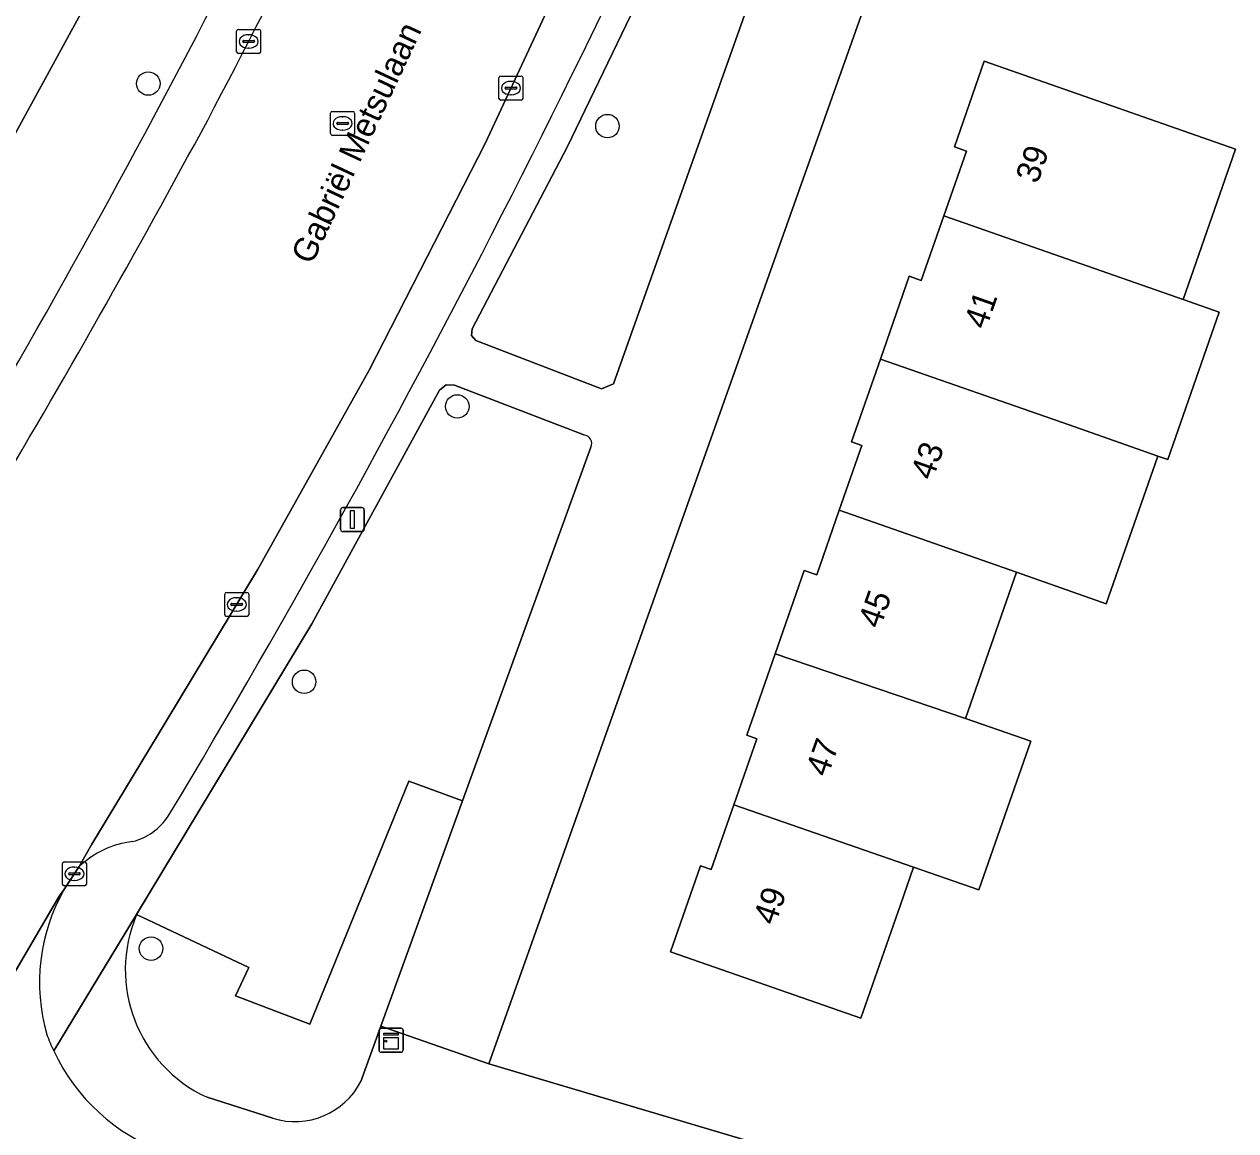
# Model space of a CAD drawing. Extents: x 161771 to 163125, y 382475 to 383179.
# Drawn here: x 162448.9 to 162499.4, y 382631.8 to 382677.9 of the extents above; entities that cross this region are included whole.
import ezdxf

# ---------------------------------------------------------------- set-up
doc = ezdxf.new("R2010")
doc.units = 0
for name, color, linetype in [('IMGEO_Boom', 7, 'Continuous'), ('IMGEO_Erf', 7, 'Continuous'), ('IMGEO_Groenvoorziening', 7, 'Continuous'), ('IMGEO_Kast', 7, 'Continuous'), ('IMGEO_Kolk', 7, 'Continuous'), ('IMGEO_Lichtmast', 7, 'Continuous'), ('IMGEO_Openbare_ruimte_label', 7, 'Continuous'), ('IMGEO_Pand', 7, 'Continuous'), ('IMGEO_Pand_nummerreeks', 7, 'Continuous'), ('IMGEO_Parkeervlak_open', 7, 'Continuous'), ('IMGEO_Rijbaan_lokaal_open', 7, 'Continuous'), ('IMGEO_Rioolput', 7, 'Continuous'), ('IMGEO_Voetpad_open', 7, 'Continuous')]:
    doc.layers.add(name, color=color, linetype=linetype)

msp = doc.modelspace()

# ---------------------------------------------------------------- linework, layer by layer
at = {"layer": 'IMGEO_Boom'}
for centre in [(162454.115, 382675.433), (162473.254, 382673.659), (162466.995, 382661.976), (162460.61, 382650.498), (162454.23, 382639.375)]:
    msp.add_circle(centre, 0.489, dxfattribs=at)
at = {"layer": 'IMGEO_Erf'}
for points in [[(162489.16, 382693.298), (162468.305, 382634.573), (162500, 382625.154)], [(162443.703, 382664.454), (162451.64, 382678.977)]]:
    msp.add_lwpolyline(points, dxfattribs=at)
msp.add_lwpolyline([(162494.048, 382653.752), (162490.306, 382655.062), (162488.177, 382648.965), (162490.896, 382648.016), (162488.733, 382641.823), (162486.015, 382642.772), (162485.465, 382641.197), (162483.816, 382636.476), (162475.887, 382639.245), (162477.138, 382642.829), (162477.58, 382642.675), (162478.521, 382645.37), (162479.482, 382648.12), (162479.059, 382648.267), (162480.242, 382651.656), (162481.457, 382655.134), (162481.976, 382654.953), (162482.917, 382657.648), (162483.858, 382660.342), (162483.424, 382660.494), (162484.63, 382663.948), (162485.835, 382667.4), (162486.331, 382667.227), (162487.272, 382669.922), (162488.215, 382672.622), (162487.714, 382672.797), (162488.958, 382676.36), (162493.679, 382674.711), (162499.437, 382672.7), (162497.246, 382666.428), (162498.756, 382665.899), (162496.613, 382659.765), (162496.202, 382659.908)], close=True, dxfattribs=at)
at = {"layer": 'IMGEO_Groenvoorziening'}
for points in [[(162475.724, 382681.413), (162471.572, 382672.776), (162467.61, 382665.208), (162467.59, 382664.935), (162467.772, 382664.73), (162473.013, 382662.713), (162473.51, 382662.915), (162479.491, 382679.788)], [(162472.269, 382660.785), (162466.878, 382662.857), (162466.525, 382662.875), (162466.257, 382662.65), (162460.926, 382652.91), (162453.63, 382640.792), (162458.301, 382638.592), (162457.753, 382637.405), (162460.849, 382636.226), (162464.97, 382646.359), (162467.218, 382645.531), (162472.565, 382660.277)], [(162467.218, 382645.531), (162464.97, 382646.359), (162460.849, 382636.226), (162457.753, 382637.405), (162458.301, 382638.592), (162453.63, 382640.792)], [(162462.978, 382633.835), (162463.814, 382636.141), (162467.218, 382645.531)], [(162456.563, 382633.183), (162459.305, 382632.306)]]:
    msp.add_lwpolyline(points, dxfattribs=at)
for centre, radius, start, end in [((162472.243, 382660.43), 0.356, 334.6119, 85.8449), ((162459, 382638.492), 5.842, 156.8173, 245.3425), ((162460.224, 382635.276), 3.109, 252.8138, 332.3883)]:
    msp.add_arc(centre, radius, start, end, dxfattribs=at)
at = {"layer": 'IMGEO_Kast'}
for p, q in [((162463.736, 382635.131), (162463.736, 382635.972)), ((162463.736, 382635.972), (162463.736, 382635.131)), ((162463.811, 382636.056), (162464.652, 382636.056)), ((162464.652, 382636.056), (162463.811, 382636.056)), ((162464.736, 382635.981), (162464.736, 382635.14)), ((162464.736, 382635.14), (162464.736, 382635.981)), ((162464.661, 382635.056), (162463.82, 382635.056)), ((162463.82, 382635.056), (162464.661, 382635.056))]:
    msp.add_line(p, q, dxfattribs=at)
for points in [[(162463.931, 382635.846), (162464.531, 382635.846), (162464.531, 382635.761), (162463.931, 382635.761), (162463.931, 382635.846)], [(162463.931, 382635.671), (162464.531, 382635.671), (162464.531, 382635.182), (162463.931, 382635.182), (162463.931, 382635.671)]]:
    msp.add_lwpolyline(points, dxfattribs=at)
msp.add_circle((162464.015, 382635.52), 0.0377, dxfattribs=at)
for centre, start, end in [((162463.814, 382635.978), 92.4484, 184.2845), ((162463.814, 382635.978), 92.4484, 184.2845), ((162464.658, 382635.978), 2.4484, 94.2845), ((162464.658, 382635.978), 2.4484, 94.2845), ((162463.814, 382635.134), 182.4484, 274.2845), ((162463.814, 382635.134), 182.4484, 274.2845), ((162464.658, 382635.134), 272.4484, 4.2845), ((162464.658, 382635.134), 272.4484, 4.2845)]:
    msp.add_arc(centre, 0.0779, start, end, dxfattribs=at)
at = {"layer": 'IMGEO_Kolk'}
for p, q in [((162457.873, 382677.688), (162458.725, 382677.688)), ((162457.798, 382676.762), (162457.798, 382677.614)), ((162458.057, 382677.182), (162458.057, 382677.194)), ((162458.495, 382677.145), (162458.097, 382677.145)), ((162458.1, 382677.231), (162458.498, 382677.231)), ((162458.286, 382677.468), (162458.311, 382677.468)), ((162458.541, 382677.194), (162458.541, 382677.182)), ((162458.799, 382677.614), (162458.799, 382676.762)), ((162458.725, 382676.688), (162457.873, 382676.688)), ((162458.309, 382676.908), (162458.284, 382676.908)), ((162468.733, 382674.817), (162468.733, 382675.669)), ((162468.808, 382675.743), (162469.66, 382675.743)), ((162469.734, 382675.669), (162469.734, 382674.817)), ((162468.992, 382675.237), (162468.992, 382675.249)), ((162469.43, 382675.2), (162469.032, 382675.2)), ((162469.035, 382675.286), (162469.433, 382675.286)), ((162469.221, 382675.523), (162469.246, 382675.523)), ((162469.476, 382675.249), (162469.476, 382675.237)), ((162469.66, 382674.743), (162468.808, 382674.743)), ((162469.244, 382674.963), (162469.219, 382674.963)), ((162457.3, 382653.295), (162457.3, 382654.147)), ((162457.375, 382654.221), (162458.227, 382654.221)), ((162457.788, 382654.001), (162457.813, 382654.001)), ((162458.301, 382654.147), (162458.301, 382653.295)), ((162457.559, 382653.715), (162457.559, 382653.727)), ((162457.997, 382653.678), (162457.599, 382653.678)), ((162457.602, 382653.764), (162458, 382653.764)), ((162457.811, 382653.441), (162457.786, 382653.441)), ((162458.043, 382653.727), (162458.043, 382653.715)), ((162458.227, 382653.221), (162457.375, 382653.221)), ((162450.534, 382642.067), (162450.534, 382642.919)), ((162450.609, 382642.993), (162451.461, 382642.993)), ((162451.022, 382642.773), (162451.047, 382642.773)), ((162451.535, 382642.919), (162451.535, 382642.067)), ((162450.793, 382642.487), (162450.793, 382642.499)), ((162451.231, 382642.45), (162450.833, 382642.45)), ((162450.836, 382642.536), (162451.234, 382642.536)), ((162451.277, 382642.499), (162451.277, 382642.487)), ((162451.461, 382641.993), (162450.609, 382641.993)), ((162451.045, 382642.213), (162451.02, 382642.213))]:
    msp.add_line(p, q, dxfattribs=at)
for points in [[(162457.873, 382677.688), (162458.725, 382677.688)], [(162457.798, 382676.762), (162457.798, 382677.614)], [(162458.799, 382677.614), (162458.799, 382676.762)], [(162458.725, 382676.688), (162457.873, 382676.688)], [(162468.733, 382674.817), (162468.733, 382675.669)], [(162468.808, 382675.743), (162469.66, 382675.743)], [(162469.734, 382675.669), (162469.734, 382674.817)], [(162469.66, 382674.743), (162468.808, 382674.743)], [(162457.3, 382653.295), (162457.3, 382654.147)], [(162457.375, 382654.221), (162458.227, 382654.221)], [(162458.301, 382654.147), (162458.301, 382653.295)], [(162458.227, 382653.221), (162457.375, 382653.221)], [(162450.534, 382642.067), (162450.534, 382642.919)], [(162450.609, 382642.993), (162451.461, 382642.993)], [(162451.535, 382642.919), (162451.535, 382642.067)], [(162451.461, 382641.993), (162450.609, 382641.993)]]:
    msp.add_lwpolyline(points, dxfattribs=at)
for centre, radius, start, end in [((162457.875, 382677.612), 0.0765, 91.552, 178.448), ((162457.875, 382677.612), 0.0765, 91.552, 178.448), ((162458.723, 382677.612), 0.0765, 1.552, 88.448), ((162458.723, 382677.612), 0.0765, 1.552, 88.448), ((162458.097, 382677.191), 0.0403, 85.8775, 175.7526), ((162458.094, 382677.181), 0.0366, 178.938, 274.7102), ((162458.498, 382677.188), 0.043, 264.8664, 352.4533), ((162458.502, 382677.193), 0.0386, 1.7309, 96.639), ((162457.875, 382676.764), 0.0765, 181.552, 268.448), ((162457.875, 382676.764), 0.0765, 181.552, 268.448), ((162458.723, 382676.764), 0.0765, 271.552, 358.448), ((162458.723, 382676.764), 0.0765, 271.552, 358.448), ((162468.81, 382675.667), 0.0765, 91.552, 178.448), ((162468.81, 382675.667), 0.0765, 91.552, 178.448), ((162469.658, 382675.667), 0.0765, 1.552, 88.448), ((162469.658, 382675.667), 0.0765, 1.552, 88.448), ((162469.032, 382675.246), 0.0403, 85.8775, 175.7526), ((162469.029, 382675.236), 0.0366, 178.938, 274.7102), ((162469.433, 382675.243), 0.043, 264.8664, 352.4533), ((162469.437, 382675.248), 0.0386, 1.7309, 96.639), ((162468.81, 382674.819), 0.0765, 181.552, 268.448), ((162468.81, 382674.819), 0.0765, 181.552, 268.448), ((162469.658, 382674.819), 0.0765, 271.552, 358.448), ((162469.658, 382674.819), 0.0765, 271.552, 358.448), ((162457.377, 382654.145), 0.0765, 91.552, 178.448), ((162457.377, 382654.145), 0.0765, 91.552, 178.448), ((162458.225, 382654.145), 0.0765, 1.552, 88.448), ((162458.225, 382654.145), 0.0765, 1.552, 88.448), ((162457.599, 382653.724), 0.0403, 85.8775, 175.7526), ((162457.596, 382653.714), 0.0366, 178.938, 274.7102), ((162458, 382653.721), 0.043, 264.8664, 352.4533), ((162458.004, 382653.726), 0.0386, 1.7309, 96.639), ((162457.377, 382653.297), 0.0765, 181.552, 268.448), ((162457.377, 382653.297), 0.0765, 181.552, 268.448), ((162458.225, 382653.297), 0.0765, 271.552, 358.448), ((162458.225, 382653.297), 0.0765, 271.552, 358.448), ((162450.611, 382642.917), 0.0765, 91.552, 178.448), ((162450.611, 382642.917), 0.0765, 91.552, 178.448), ((162451.459, 382642.917), 0.0765, 1.552, 88.448), ((162451.459, 382642.917), 0.0765, 1.552, 88.448), ((162450.833, 382642.496), 0.0403, 85.8775, 175.7526), ((162450.83, 382642.486), 0.0366, 178.938, 274.7102), ((162451.234, 382642.493), 0.043, 264.8664, 352.4533), ((162451.238, 382642.498), 0.0386, 1.7309, 96.639), ((162450.611, 382642.069), 0.0765, 181.552, 268.448), ((162450.611, 382642.069), 0.0765, 181.552, 268.448), ((162451.459, 382642.069), 0.0765, 271.552, 358.448), ((162451.459, 382642.069), 0.0765, 271.552, 358.448)]:
    msp.add_arc(centre, radius, start, end, dxfattribs=at)
for centre, major_axis, ratio, start_param, end_param in [((162458.285, 382677.188), (-0.387, 0.002), 0.722429, 4.712389, 7.853982), ((162458.31, 382677.188), (-0.39, 0.002), 0.717154, 1.570796, 4.712389), ((162469.22, 382675.243), (-0.387, 0.002), 0.722429, 4.712389, 7.853982), ((162469.245, 382675.243), (-0.39, 0.002), 0.717154, 1.570796, 4.712389), ((162457.787, 382653.721), (-0.387, 0.002), 0.722429, 4.712389, 7.853982), ((162457.812, 382653.721), (-0.39, 0.002), 0.717154, 1.570796, 4.712389), ((162451.021, 382642.493), (-0.387, 0.002), 0.722429, 4.712389, 7.853982), ((162451.046, 382642.493), (-0.39, 0.002), 0.717154, 1.570796, 4.712389)]:
    msp.add_ellipse(centre, major_axis=major_axis, ratio=ratio, start_param=start_param, end_param=end_param, dxfattribs=at)
at = {"layer": 'IMGEO_Lichtmast'}
for p, q in [((162462.129, 382656.86), (162462.129, 382657.66)), ((162462.129, 382657.66), (162462.129, 382656.86)), ((162462.229, 382657.76), (162463.019, 382657.76)), ((162463.019, 382657.76), (162462.229, 382657.76)), ((162463.119, 382657.66), (162463.119, 382656.86)), ((162463.119, 382656.86), (162463.119, 382657.66)), ((162463.019, 382656.76), (162462.229, 382656.76)), ((162462.229, 382656.76), (162463.019, 382656.76))]:
    msp.add_line(p, q, dxfattribs=at)
msp.add_lwpolyline([(162462.549, 382657.635), (162462.699, 382657.635), (162462.699, 382656.885), (162462.549, 382656.885), (162462.549, 382657.635)], dxfattribs=at)
for centre, start, end in [((162462.229, 382657.66), 90, 180), ((162462.229, 382657.66), 90, 180), ((162463.019, 382657.66), 0, 90), ((162463.019, 382657.66), 360, 90), ((162462.229, 382656.86), 180, 270), ((162462.229, 382656.86), 180, 270), ((162463.019, 382656.86), 270, 0), ((162463.019, 382656.86), 270, 0)]:
    msp.add_arc(centre, 0.1, start, end, dxfattribs=at)
at = {"layer": 'IMGEO_Pand'}
for points in [[(162497.246, 382666.428), (162499.437, 382672.7), (162493.679, 382674.711), (162488.958, 382676.36), (162487.714, 382672.797), (162488.215, 382672.622), (162487.272, 382669.922)], [(162498.756, 382665.899), (162497.246, 382666.428), (162487.272, 382669.922), (162486.331, 382667.227), (162485.835, 382667.4), (162484.63, 382663.948), (162492.456, 382661.217), (162495.103, 382660.292), (162496.202, 382659.908), (162496.613, 382659.765)], [(162496.202, 382659.908), (162495.103, 382660.292), (162492.456, 382661.217), (162484.63, 382663.948), (162483.424, 382660.494), (162483.858, 382660.342), (162482.917, 382657.648), (162490.306, 382655.062), (162494.048, 382653.752)], [(162488.177, 382648.965), (162490.306, 382655.062), (162482.917, 382657.648), (162481.976, 382654.953), (162481.457, 382655.134), (162480.242, 382651.656)], [(162488.177, 382648.965), (162480.242, 382651.656), (162479.059, 382648.267), (162479.482, 382648.12), (162478.521, 382645.37), (162486.015, 382642.772), (162488.733, 382641.823), (162490.896, 382648.016)], [(162478.521, 382645.37), (162477.58, 382642.675), (162477.138, 382642.829), (162475.887, 382639.245), (162483.816, 382636.476), (162485.465, 382641.197), (162486.015, 382642.772)]]:
    msp.add_lwpolyline(points, close=True, dxfattribs=at)
at = {"layer": 'IMGEO_Parkeervlak_open'}
msp.add_lwpolyline([(162512.632, 382808.546), (162511.28, 382810.646), (162509.154, 382801.926), (162505.086, 382785.036), (162500.442, 382764.689), (162500, 382762.664), (162498.277, 382754.772), (162497.178, 382750), (162496.887, 382748.736), (162496.008, 382745.127), (162493.813, 382737.211), (162492.079, 382731.423), (162488.748, 382721.634), (162487.266, 382717.521), (162483.52, 382707.553), (162479.897, 382698.492), (162476.717, 382691.181), (162472.466, 382682.195), (162468.158, 382672.932), (162463.316, 382663.492), (162458.673, 382655.168), (162454.89, 382648.901), (162451.763, 382643.729), (162451.23, 382642.792)], dxfattribs=at)
for centre, radius, start, end in [((162182.598, 382819.036), 310.052, 332.0916, 339.45199), ((162091.344, 382862.892), 423.95, 329.05493, 337.05894), ((162116.582, 382854.367), 382.886, 329.58715, 333.2852), ((162074.96, 382879.557), 433.51, 326.74218, 331.68168), ((162452.816, 382646.334), 2.575, 284.5682, 325.9064), ((162453.965, 382639.871), 4.001, 97.1898, 133.1161)]:
    msp.add_arc(centre, radius, start, end, dxfattribs=at)
at = {"layer": 'IMGEO_Rijbaan_lokaal_open'}
for points in [[(162404.135, 382574.905), (162406.193, 382577.683), (162407.992, 382580.104), (162411.216, 382584.51), (162411.282, 382584.599), (162428.004, 382607.232), (162439.892, 382623.551), (162440.057, 382623.883), (162450.381, 382641.534), (162450.597, 382641.828), (162451.23, 382642.792), (162451.763, 382643.729), (162454.89, 382648.901), (162458.673, 382655.168), (162463.316, 382663.492), (162468.158, 382672.932), (162472.466, 382682.195)], [(162450.597, 382641.828), (162450.381, 382641.534), (162440.057, 382623.883), (162439.892, 382623.551)]]:
    msp.add_lwpolyline(points, dxfattribs=at)
for centre, radius, start, end in [((162182.598, 382819.036), 310.052, 332.0916, 339.45199), ((162074.96, 382879.557), 433.51, 326.74218, 331.68168), ((162457.39, 382637.972), 7.811, 150.4156, 196.179), ((162457.259, 382638.46), 7.838, 199.8736, 205.2827), ((162457.608, 382638.596), 8.212, 205.1066, 249.9523)]:
    msp.add_arc(centre, radius, start, end, dxfattribs=at)
at = {"layer": 'IMGEO_Rioolput'}
for p, q in [((162461.715, 382673.346), (162461.715, 382674.198)), ((162461.79, 382674.272), (162462.642, 382674.272)), ((162462.716, 382674.198), (162462.716, 382673.346)), ((162461.974, 382673.766), (162461.974, 382673.778)), ((162462.412, 382673.729), (162462.014, 382673.729)), ((162462.017, 382673.815), (162462.415, 382673.815)), ((162462.203, 382674.052), (162462.228, 382674.052)), ((162462.458, 382673.778), (162462.458, 382673.766)), ((162462.642, 382673.272), (162461.79, 382673.272)), ((162462.226, 382673.492), (162462.201, 382673.492))]:
    msp.add_line(p, q, dxfattribs=at)
for points in [[(162461.715, 382673.346), (162461.715, 382674.198)], [(162461.79, 382674.272), (162462.642, 382674.272)], [(162462.716, 382674.198), (162462.716, 382673.346)], [(162462.642, 382673.272), (162461.79, 382673.272)]]:
    msp.add_lwpolyline(points, dxfattribs=at)
for centre, radius, start, end in [((162461.792, 382674.196), 0.0765, 91.552, 178.448), ((162461.792, 382674.196), 0.0765, 91.552, 178.448), ((162462.64, 382674.196), 0.0765, 1.552, 88.448), ((162462.64, 382674.196), 0.0765, 1.552, 88.448), ((162462.014, 382673.775), 0.0403, 85.8775, 175.7526), ((162462.011, 382673.765), 0.0366, 178.938, 274.7102), ((162462.415, 382673.772), 0.043, 264.8664, 352.4533), ((162462.419, 382673.777), 0.0386, 1.7309, 96.639), ((162461.792, 382673.348), 0.0765, 181.552, 268.448), ((162461.792, 382673.348), 0.0765, 181.552, 268.448), ((162462.64, 382673.348), 0.0765, 271.552, 358.448), ((162462.64, 382673.348), 0.0765, 271.552, 358.448)]:
    msp.add_arc(centre, radius, start, end, dxfattribs=at)
for centre, major_axis, ratio, start_param, end_param in [((162462.202, 382673.772), (-0.387, 0.002), 0.722429, 4.712389, 7.853982), ((162462.227, 382673.772), (-0.39, 0.002), 0.717154, 1.570796, 4.712389)]:
    msp.add_ellipse(centre, major_axis=major_axis, ratio=ratio, start_param=start_param, end_param=end_param, dxfattribs=at)
at = {"layer": 'IMGEO_Voetpad_open'}
for points in [[(162472.565, 382660.277), (162467.218, 382645.531), (162463.814, 382636.141), (162468.305, 382634.573), (162489.16, 382693.298), (162492.061, 382702.197), (162492.531, 382703.794), (162496.253, 382716.455), (162500, 382730.308), (162503.472, 382745.528), (162503.806, 382746.991), (162504.492, 382750), (162508.826, 382769.514), (162509.13, 382770.881), (162519.291, 382816.631)], [(162483.186, 382760.323), (162482.438, 382760.49), (162481.155, 382756.282), (162479.277, 382750), (162475.552, 382737.539), (162469.715, 382720.652), (162462.007, 382700.842), (162457.539, 382690.752), (162451.64, 382678.977), (162443.703, 382664.454), (162438.387, 382655.596), (162432.385, 382646.085), (162421.193, 382630.033), (162412.885, 382618.959), (162400.55, 382603.937), (162397.717, 382600.824), (162401.803, 382597.737), (162402.538, 382596.903), (162403.952, 382598.14), (162405.935, 382599.931), (162406.248, 382600.285)], [(162479.491, 382679.788), (162473.51, 382662.915), (162473.013, 382662.713), (162467.772, 382664.73), (162467.59, 382664.935), (162467.61, 382665.208), (162471.572, 382672.776), (162475.724, 382681.413)], [(162450.172, 382635.112), (162453.63, 382640.792), (162460.926, 382652.91), (162466.257, 382662.65), (162466.525, 382662.875), (162466.878, 382662.857), (162472.269, 382660.785)], [(162451.23, 382642.792), (162450.597, 382641.828)], [(162453.63, 382640.792), (162450.172, 382635.112)], [(162562.442, 382606.621), (162559.118, 382607.586), (162531.953, 382615.658), (162530.512, 382616.086), (162505.275, 382623.586), (162500.101, 382625.124), (162500, 382625.154), (162468.305, 382634.573), (162463.814, 382636.141), (162462.978, 382633.835)], [(162459.305, 382632.306), (162456.563, 382633.183)]]:
    msp.add_lwpolyline(points, dxfattribs=at)
for centre, radius, start, end in [((162091.344, 382862.892), 423.95, 329.05493, 337.05894), ((162116.582, 382854.367), 382.886, 329.58715, 333.2852), ((162472.243, 382660.43), 0.356, 334.6119, 85.8449), ((162452.816, 382646.334), 2.575, 284.5682, 325.9064), ((162453.965, 382639.871), 4.001, 97.1898, 133.1161), ((162457.39, 382637.972), 7.811, 150.4156, 196.179), ((162459, 382638.492), 5.842, 156.8173, 245.3425), ((162457.259, 382638.46), 7.838, 199.8736, 205.2827), ((162457.608, 382638.596), 8.212, 205.1066, 249.9523), ((162460.224, 382635.276), 3.109, 252.8138, 332.3883)]:
    msp.add_arc(centre, radius, start, end, dxfattribs=at)

# ---------------------------------------------------------------- texts
at = {"layer": 'IMGEO_Openbare_ruimte_label'}
msp.add_text('Gabriël Metsulaan', height=1, rotation=64.9208, dxfattribs=at).set_placement((162460.933, 382667.846))
at = {"layer": 'IMGEO_Pand_nummerreeks'}
for s, rotation, p in [('39', 70.5062, (162491.182, 382671.22)), ('41', 70.5082, (162489.03, 382665.145)), ('43', 70.5082, (162486.804, 382658.856)), ('45', 70.5062, (162484.616, 382652.673)), ('47', 70.5062, (162482.428, 382646.491)), ('49', 70.5062, (162480.239, 382640.308))]:
    msp.add_text(s, height=1, rotation=rotation, dxfattribs=at).set_placement(p)

doc.saveas('drawing.dxf')
